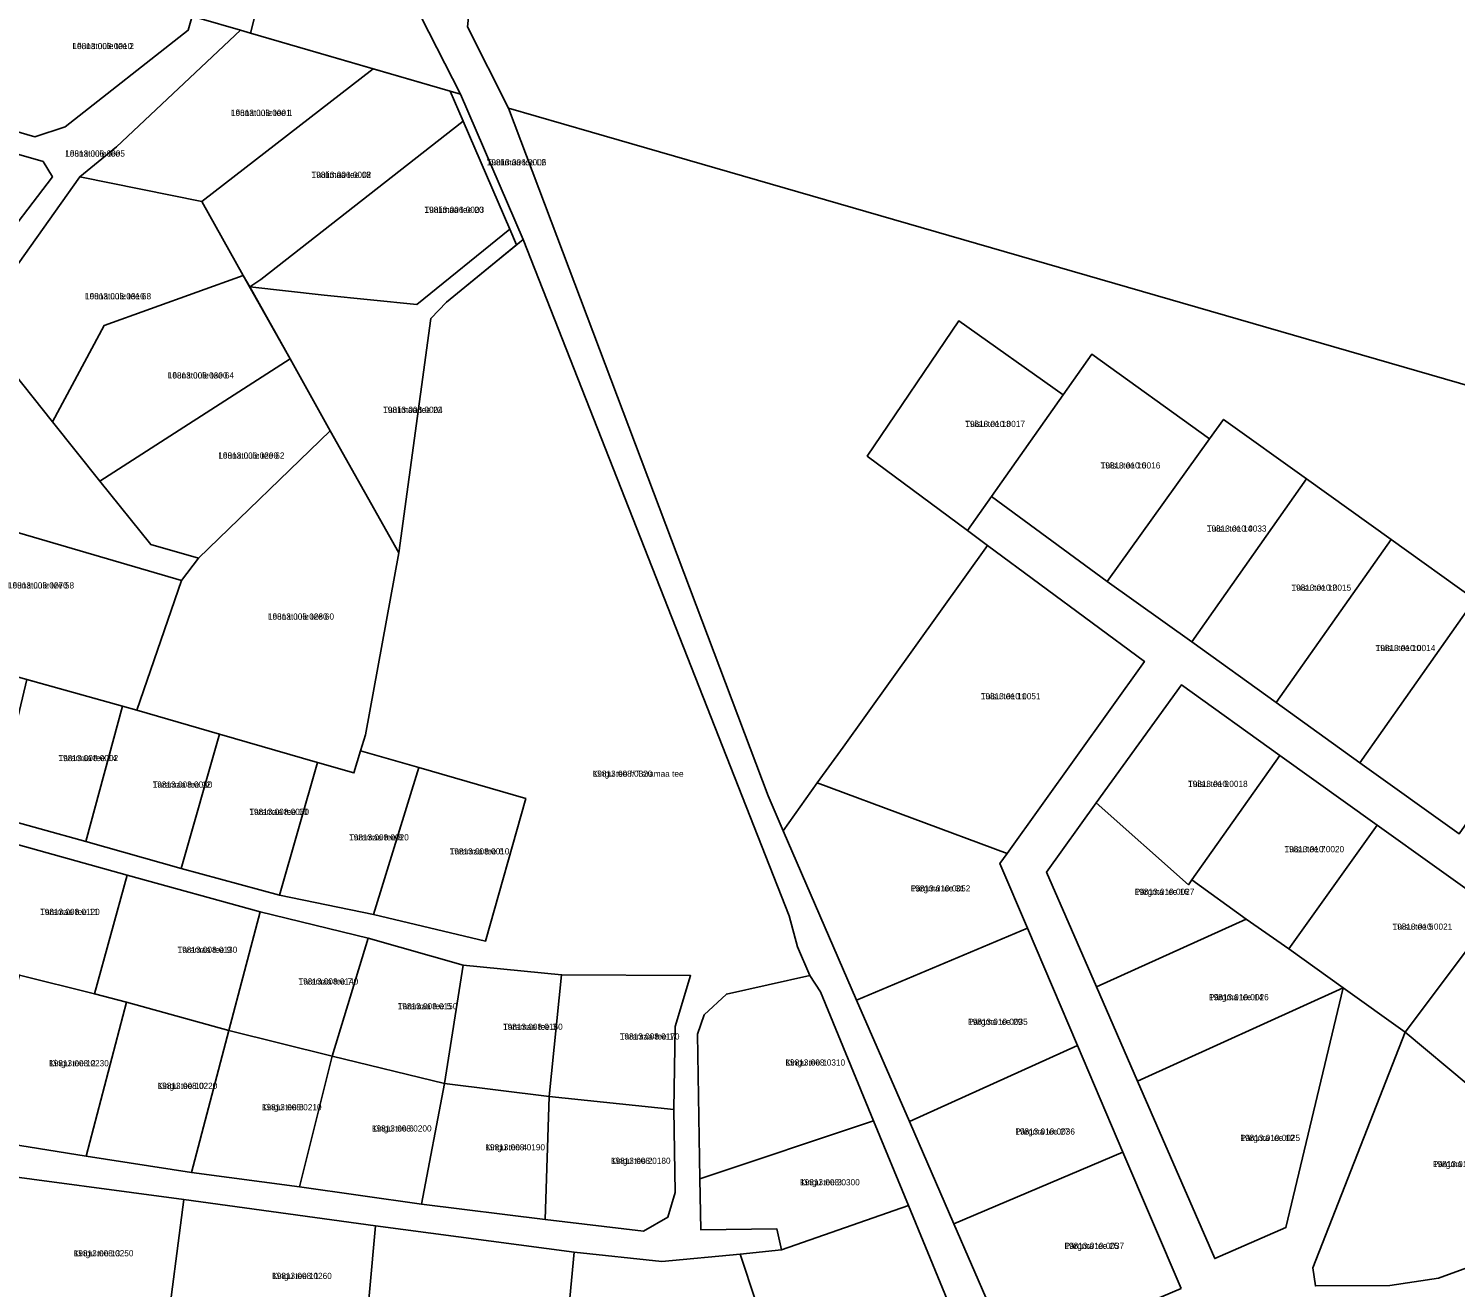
# Model space of a CAD drawing. Extents: x 516875 to 535633, y 6574491 to 6593094.
# Drawn here: x 518002.1 to 518348.7, y 6583536.8 to 6583842.6 of the extents above; entities that cross this region are included whole.
import ezdxf

# ---------------------------------------------------------------- set-up
doc = ezdxf.new("R2010")
doc.units = 0
for name, color, linetype in [('L_AADRESS', 7, 'Continuous'), ('PIIR', 7, 'Continuous'), ('TUNNUS', 7, 'Continuous')]:
    doc.layers.add(name, color=color, linetype=linetype)

msp = doc.modelspace()

# ---------------------------------------------------------------- linework, layer by layer
at = {"layer": 'PIIR'}
for points in [[(518119.68, 6583947.56), (518148.5, 6583950.08), (518165.33, 6583915.79), (518195.67, 6583852.92), (518252, 6583881.49), (518277.31, 6583894.33), (518313.45, 6583912.04), (518337.66, 6583924.16), (518350.53, 6583930.55), (518369.36, 6583908.16), (518395.02, 6583877.64), (518410.83, 6583858.99), (518420.56, 6583835.4), (518428.46, 6583811.8), (518412.68, 6583808.85), (518379.77, 6583802.71), (518366.15, 6583751.74), (518138.79, 6583817.44), (518118.62, 6583823.27), (518108.69, 6583843.02)], [(518055.95, 6583841.51), (518070.47, 6583898.22), (518106.97, 6583826.68)], [(517985.74, 6583821.48), (517996.62, 6583858.9), (518015.14, 6583853.46), (518041.8, 6583845.63), (518040.85, 6583842.21), (518010.97, 6583818.73), (518003.6, 6583816.35)], [(518014.49, 6583806.61), (518023.41, 6583813.86), (518053.55, 6583842.21), (518055.95, 6583841.51), (518085.8, 6583832.84), (518044.11, 6583800.59)], [(518044.11, 6583800.59), (518085.8, 6583832.84), (518104.51, 6583827.4), (518107.64, 6583820.12), (518058.52, 6583781.66), (518055.78, 6583779.84), (518054.22, 6583782.6)], [(518104.51, 6583827.4), (518106.97, 6583826.68), (518122.17, 6583791.38), (518120.58, 6583790.08), (518118.93, 6583793.9), (518107.64, 6583820.12)], [(517964.46, 6583782.19), (517975, 6583819.05), (518005.57, 6583810.32), (518007.86, 6583806.63), (517979.17, 6583768.99)], [(518055.78, 6583779.84), (518058.52, 6583781.66), (518107.64, 6583820.12), (518118.93, 6583793.9), (518096.38, 6583775.57), (518073.9, 6583777.89)], [(518007.89, 6583747.09), (517989.02, 6583770.74), (518014.49, 6583806.61), (518044.11, 6583800.59), (518054.22, 6583782.6), (518020.39, 6583770.47)], [(518055.78, 6583779.84), (518073.9, 6583777.89), (518096.38, 6583775.57), (518118.93, 6583793.9), (518120.58, 6583790.08), (518103.57, 6583776.17), (518099.81, 6583772.15), (518092.03, 6583715.27), (518075.34, 6583744.9), (518065.63, 6583762.37)], [(518007.89, 6583747.09), (518020.39, 6583770.47), (518054.22, 6583782.6), (518065.63, 6583762.37), (518019.38, 6583732.64)], [(518205.78, 6583738.76), (518228.05, 6583771.63), (518253.4, 6583753.68), (518235.99, 6583728.96), (518230.15, 6583720.7)], [(518031.72, 6583717.26), (518019.38, 6583732.64), (518065.63, 6583762.37), (518075.34, 6583744.9), (518043.34, 6583713.93)], [(518253.4, 6583753.68), (518260.34, 6583763.55), (518288.95, 6583742.96), (518264.03, 6583708.34), (518235.99, 6583728.96)], [(518312.5, 6583733.22), (518284.6, 6583693.61), (518264.03, 6583708.34), (518288.95, 6583742.96), (518292.34, 6583747.67)], [(518028.36, 6583677.02), (518039.22, 6583708.54), (518043.34, 6583713.93), (518075.34, 6583744.9), (518092.03, 6583715.27), (518083.9, 6583671.04), (518082.73, 6583667.2), (518081.09, 6583661.82), (518072.24, 6583664.37), (518048.47, 6583671.22)], [(517965.25, 6583736.2), (517983.25, 6583724.94), (518039.22, 6583708.54), (518028.36, 6583677.02), (518024.91, 6583677.99), (517952.8, 6583698.13)], [(518284.6, 6583693.61), (518312.5, 6583733.22), (518333.06, 6583718.48), (518305.14, 6583678.89)], [(518235.01, 6583717.06), (518273.09, 6583688.9), (518239.74, 6583642.24), (518193.65, 6583659.39), (518199.91, 6583668.1)], [(518353.39, 6583703.91), (518325.45, 6583664.29), (518305.14, 6583678.89), (518333.06, 6583718.48)], [(518377.24, 6583686.82), (518349.53, 6583646.99), (518325.45, 6583664.29), (518353.39, 6583703.91)], [(518001.68, 6583684.47), (518024.91, 6583677.99), (518015.95, 6583645.18), (517993.73, 6583651.3)], [(518282.11, 6583683.2), (518261.37, 6583654.52), (518249.36, 6583637.7), (518261.48, 6583609.85), (518271.45, 6583586.92), (518290.19, 6583543.83), (518307.48, 6583551.35), (518321.39, 6583609.64), (518336.44, 6583598.86), (518314.01, 6583541.62), (518314.63, 6583537.2), (518332.71, 6583537.27), (518344.56, 6583539.12), (518357.63, 6583543.89), (518372.37, 6583550.53), (518405.69, 6583565.75), (518388.93, 6583602.34), (518384.82, 6583609.06), (518358.61, 6583628.41), (518329.61, 6583649.1), (518306.01, 6583666.04)], [(518284.65, 6583635.87), (518283.78, 6583634.65), (518261.37, 6583654.52), (518282.11, 6583683.2), (518306.01, 6583666.04)], [(518024.91, 6583677.99), (518028.36, 6583677.02), (518048.47, 6583671.22), (518039.14, 6583638.59), (518015.95, 6583645.18)], [(518048.47, 6583671.22), (518072.24, 6583664.37), (518063.01, 6583632.1), (518039.14, 6583638.59)], [(518072.24, 6583664.37), (518081.09, 6583661.82), (518082.73, 6583667.2), (518096.83, 6583663.12), (518085.85, 6583627.45), (518063.01, 6583632.1)], [(518306.01, 6583666.04), (518329.61, 6583649.1), (518308.18, 6583619.11), (518297.85, 6583626.26), (518284.65, 6583635.87)], [(518096.83, 6583663.12), (518122.85, 6583655.61), (518113.07, 6583620.97), (518085.85, 6583627.45)], [(518193.65, 6583659.39), (518239.74, 6583642.24), (518238, 6583639.81), (518244.68, 6583624.13), (518203.2, 6583606.62), (518185.32, 6583647.76)], [(518283.78, 6583634.65), (518284.65, 6583635.87), (518297.85, 6583626.26), (518261.48, 6583609.85), (518249.36, 6583637.7), (518261.37, 6583654.52)], [(518358.61, 6583628.41), (518336.44, 6583598.86), (518321.39, 6583609.64), (518308.18, 6583619.11), (518329.61, 6583649.1)], [(517982.9, 6583615.4), (517992.02, 6583646.47), (518025.99, 6583637), (518018.05, 6583608.13), (517999.87, 6583612.71)], [(518018.05, 6583608.13), (518025.99, 6583637), (518058.33, 6583628.04), (518050.72, 6583599.22), (518025.85, 6583606.16)], [(518058.33, 6583628.04), (518084.57, 6583621.7), (518075.8, 6583593), (518050.72, 6583599.22)], [(518384.82, 6583609.06), (518388.93, 6583602.34), (518354.21, 6583587.15), (518351.72, 6583586.06), (518336.44, 6583598.86), (518358.61, 6583628.41)], [(518256.84, 6583595.61), (518216.03, 6583577.1), (518203.2, 6583606.62), (518244.68, 6583624.13)], [(518308.18, 6583619.11), (518321.39, 6583609.64), (518271.45, 6583586.92), (518261.48, 6583609.85), (518297.85, 6583626.26)], [(518084.57, 6583621.7), (518107.66, 6583615.14), (518103.08, 6583586.36), (518075.8, 6583593)], [(517999.87, 6583612.71), (518018.05, 6583608.13), (518025.85, 6583606.16), (518016.08, 6583568.73), (517988.26, 6583573.2)], [(518107.66, 6583615.14), (518131.52, 6583612.77), (518128.49, 6583583.23), (518103.08, 6583586.36)], [(518131.52, 6583612.77), (518162.86, 6583612.56), (518159.13, 6583600.22), (518158.79, 6583580.04), (518128.49, 6583583.23)], [(518164.52, 6583598.34), (518166.18, 6583603.04), (518171.58, 6583608.1), (518191.8, 6583612.62), (518194.41, 6583608.65), (518207.3, 6583577.32), (518165.14, 6583563.17)], [(518307.48, 6583551.35), (518290.19, 6583543.83), (518271.45, 6583586.92), (518321.39, 6583609.64)], [(518025.85, 6583606.16), (518050.72, 6583599.22), (518041.66, 6583564.76), (518016.08, 6583568.73)], [(518050.72, 6583599.22), (518075.8, 6583593), (518067.84, 6583561.28), (518041.66, 6583564.76)], [(518351.72, 6583586.06), (518354.21, 6583587.15), (518372.37, 6583550.53), (518357.63, 6583543.89), (518344.56, 6583539.12), (518332.71, 6583537.27), (518314.63, 6583537.2), (518314.01, 6583541.62), (518336.44, 6583598.86)], [(518267.87, 6583569.7), (518226.8, 6583552.31), (518216.03, 6583577.1), (518256.84, 6583595.61)], [(518075.8, 6583593), (518103.08, 6583586.36), (518097.53, 6583557.03), (518067.84, 6583561.28)], [(518103.08, 6583586.36), (518128.49, 6583583.23), (518127.58, 6583553.32), (518097.53, 6583557.03)], [(518128.49, 6583583.23), (518158.79, 6583580.04), (518159.15, 6583559.91), (518157.32, 6583553.86), (518151.41, 6583550.46), (518127.58, 6583553.32)], [(518183.8, 6583551.1), (518165.36, 6583550.8), (518165.14, 6583563.17), (518207.3, 6583577.32), (518215.77, 6583556.7), (518184.92, 6583545.95)], [(518282.02, 6583536.54), (518252.26, 6583523.93), (518239.67, 6583522.67), (518226.8, 6583552.31), (518267.87, 6583569.7)], [(517990.05, 6583564.86), (518039.75, 6583558.17), (518035.35, 6583523.9), (517986.57, 6583528.25)], [(518039.75, 6583558.17), (518086.33, 6583551.78), (518083.42, 6583519.61), (518035.35, 6583523.9)], [(518174.88, 6583544.93), (518184.92, 6583545.95), (518215.77, 6583556.7), (518232.29, 6583516.55), (518231.48, 6583512.69), (518229.22, 6583508.9), (518226.28, 6583506.86), (518186.36, 6583510.43)], [(518086.33, 6583551.78), (518134.58, 6583545.36), (518131.79, 6583515.29), (518083.42, 6583519.61)], [(518134.58, 6583545.36), (518155.86, 6583543.14), (518174.88, 6583544.93), (518186.36, 6583510.43), (518131.79, 6583515.29)]]:
    msp.add_lwpolyline(points, close=True, dxfattribs=at)
for points in [[(518232.29, 6583516.55), (518215.77, 6583556.7), (518207.3, 6583577.32), (518194.41, 6583608.65), (518191.8, 6583612.62), (518188.85, 6583619.6), (518186.83, 6583627.11), (518122.17, 6583791.38), (518106.97, 6583826.68), (518070.47, 6583898.22), (518055.95, 6583841.51), (518053.55, 6583842.21), (518043.38, 6583845.17)], [(517985.74, 6583821.48), (518003.6, 6583816.35), (518010.97, 6583818.73), (518040.85, 6583842.21), (518041.8, 6583845.63), (518043.38, 6583845.17), (518053.55, 6583842.21), (518023.41, 6583813.86), (518014.49, 6583806.61), (517989.02, 6583770.74), (518007.89, 6583747.09), (518019.38, 6583732.64), (518031.72, 6583717.26), (518043.34, 6583713.93), (518039.22, 6583708.54), (517983.25, 6583724.94)], [(518108.69, 6583843.02), (518118.62, 6583823.27), (518181.72, 6583656.25), (518185.32, 6583647.76), (518203.2, 6583606.62), (518216.03, 6583577.1), (518226.8, 6583552.31), (518239.67, 6583522.67)], [(518353.39, 6583703.91), (518333.06, 6583718.48), (518312.5, 6583733.22), (518292.34, 6583747.67), (518288.95, 6583742.96), (518260.34, 6583763.55), (518253.4, 6583753.68), (518228.05, 6583771.63), (518205.78, 6583738.76), (518230.15, 6583720.7), (518235.01, 6583717.06), (518199.91, 6583668.1), (518193.65, 6583659.39), (518185.32, 6583647.76), (518181.72, 6583656.25), (518118.62, 6583823.27), (518138.79, 6583817.44), (518366.15, 6583751.74)], [(517979.17, 6583768.99), (518007.86, 6583806.63), (518005.57, 6583810.32), (517975, 6583819.05)], [(517993.73, 6583651.3), (518015.95, 6583645.18), (518039.14, 6583638.59), (518063.01, 6583632.1), (518085.85, 6583627.45), (518113.07, 6583620.97), (518122.85, 6583655.61), (518096.83, 6583663.12), (518082.73, 6583667.2), (518083.9, 6583671.04), (518092.03, 6583715.27), (518099.81, 6583772.15), (518103.57, 6583776.17), (518122.17, 6583791.38), (518186.83, 6583627.11), (518188.85, 6583619.6), (518191.8, 6583612.62), (518171.58, 6583608.1), (518166.18, 6583603.04), (518164.52, 6583598.34), (518165.14, 6583563.17), (518165.36, 6583550.8), (518183.8, 6583551.1), (518184.92, 6583545.95), (518174.88, 6583544.93), (518155.86, 6583543.14), (518134.58, 6583545.36), (518086.33, 6583551.78), (518039.75, 6583558.17), (517990.05, 6583564.86)], [(518282.02, 6583536.54), (518267.87, 6583569.7), (518256.84, 6583595.61), (518244.68, 6583624.13), (518238, 6583639.81), (518239.74, 6583642.24), (518273.09, 6583688.9), (518235.01, 6583717.06), (518230.15, 6583720.7), (518235.99, 6583728.96), (518264.03, 6583708.34), (518284.6, 6583693.61), (518305.14, 6583678.89), (518325.45, 6583664.29), (518349.53, 6583646.99)], [(517988.26, 6583573.2), (518016.08, 6583568.73), (518041.66, 6583564.76), (518067.84, 6583561.28), (518097.53, 6583557.03), (518127.58, 6583553.32), (518151.41, 6583550.46), (518157.32, 6583553.86), (518159.15, 6583559.91), (518158.79, 6583580.04), (518159.13, 6583600.22), (518162.86, 6583612.56), (518131.52, 6583612.77), (518107.66, 6583615.14), (518084.57, 6583621.7), (518058.33, 6583628.04), (518025.99, 6583637), (517992.02, 6583646.47)]]:
    msp.add_lwpolyline(points, dxfattribs=at)

# ---------------------------------------------------------------- texts
at = {"layer": 'L_AADRESS'}
for s, p in [('Lõunatuule tee 2', (518012.72, 6583837.62)), ('Lõunatuule tee 1', (518051.22, 6583821.4)), ('Lõunatuule tee', (518010.96, 6583811.51)), ('Tuulimaa tee L2', (518113.34, 6583809.38)), ('Tuulimaa tee 18', (518070.79, 6583806.34)), ('Tuulimaa tee 20', (518098.21, 6583797.85)), ('Lõunatuule tee 68', (518015.77, 6583776.85)), ('Lõunatuule tee 64', (518035.88, 6583757.62)), ('Tuulimaa tee 22', (518088.18, 6583749.26)), ('Tuisu tee 18', (518229.59, 6583745.83)), ('Lõunatuule tee 62', (518048.16, 6583738.15)), ('Tuisu tee 16', (518262.47, 6583735.75)), ('Tuisu tee 14', (518288.27, 6583720.41)), ('Lõunatuule tee 58', (517997.06, 6583706.61)), ('Tuisu tee 12', (518308.83, 6583706.07)), ('Lõunatuule tee 60', (518060.2, 6583699.04)), ('Tuisu tee 10', (518329.27, 6583691.4)), ('Tuisu tee 11', (518233.37, 6583679.69)), ('Taramaa tee 14', (518009.32, 6583664.67)), ('Kingu tee // Taramaa tee', (518139.09, 6583660.87)), ('Taramaa tee 12', (518032.21, 6583658.23)), ('Tuisu tee 9', (518283.69, 6583658.4)), ('Taramaa tee 10', (518055.69, 6583651.61)), ('Taramaa tee 8', (518079.92, 6583645.41)), ('Tuisu tee 7', (518307.13, 6583642.54)), ('Taramaa tee 6', (518104.35, 6583642)), ('Pärgma tee 31', (518216.32, 6583633.01)), ('Pärgma tee 16', (518270.74, 6583632.19)), ('Taramaa tee 11', (518004.86, 6583627.3)), ('Tuisu tee 5', (518333.39, 6583623.72)), ('Taramaa tee 9', (518038.25, 6583618.11)), ('Taramaa tee 7', (518067.64, 6583610.41)), ('Taramaa tee 5', (518091.73, 6583604.39)), ('Pärgma tee 14', (518288.79, 6583606.59)), ('Pärgma tee 29', (518230.26, 6583600.62)), ('Taramaa tee 3', (518117.3, 6583599.4)), ('Taramaa tee 1', (518145.68, 6583597.05)), ('Kingu tee 12', (518007.05, 6583590.54)), ('Kingu tee 1', (518185.91, 6583590.72)), ('Kingu tee 10', (518033.4, 6583585.05)), ('Kingu tee 8', (518058.73, 6583579.86)), ('Kingu tee 6', (518085.46, 6583574.7)), ('Pärgma tee 27', (518241.73, 6583573.96)), ('Kingu tee 4', (518113.01, 6583570.13)), ('Pärgma tee 12', (518296.42, 6583572.41)), ('Kingu tee 2', (518143.51, 6583566.85)), ('Pärgma tee 10', (518343.19, 6583566.06)), ('Kingu tee 3', (518189.46, 6583561.63)), ('Pärgma tee 25', (518253.68, 6583546.19)), ('Kingu tee 13', (518013.04, 6583544.38)), ('Kingu tee 11', (518061.22, 6583538.89))]:
    msp.add_text(s, height=1.5, dxfattribs=at).set_placement(p)
at = {"layer": 'TUNNUS'}
for s, p in [('19813:006:0010', (518012.72, 6583837.62)), ('19813:006:0001', (518051.22, 6583821.4)), ('19813:006:0005', (518010.96, 6583811.51)), ('19813:006:0006', (518113.34, 6583809.38)), ('19813:006:0002', (518070.79, 6583806.34)), ('19813:006:0003', (518098.21, 6583797.85)), ('19813:006:0310', (518015.77, 6583776.85)), ('19813:006:0300', (518035.88, 6583757.62)), ('19813:006:0004', (518088.18, 6583749.26)), ('19813:010:0017', (518229.59, 6583745.83)), ('19813:006:0290', (518048.16, 6583738.15)), ('19813:010:0016', (518262.47, 6583735.75)), ('19813:010:0033', (518288.27, 6583720.41)), ('19813:006:0270', (517997.06, 6583706.61)), ('19813:010:0015', (518308.83, 6583706.07)), ('19813:006:0280', (518060.2, 6583699.04)), ('19813:010:0014', (518329.27, 6583691.4)), ('19813:010:0051', (518233.37, 6583679.69)), ('19813:008:0002', (518009.32, 6583664.67)), ('19813:008:0320', (518139.09, 6583660.87)), ('19813:008:0040', (518032.21, 6583658.23)), ('19813:010:0018', (518283.69, 6583658.4)), ('19813:008:0030', (518055.69, 6583651.61)), ('19813:008:0020', (518079.92, 6583645.41)), ('19813:010:0020', (518307.13, 6583642.54)), ('19813:008:0010', (518104.35, 6583642)), ('19813:010:0052', (518216.32, 6583633.01)), ('19813:010:0027', (518270.74, 6583632.19)), ('19813:008:0120', (518004.86, 6583627.3)), ('19813:010:0021', (518333.39, 6583623.72)), ('19813:008:0130', (518038.25, 6583618.11)), ('19813:008:0140', (518067.64, 6583610.41)), ('19813:008:0150', (518091.73, 6583604.39)), ('19813:010:0026', (518288.79, 6583606.59)), ('19813:010:0035', (518230.26, 6583600.62)), ('19813:008:0160', (518117.3, 6583599.4)), ('19813:008:0170', (518145.68, 6583597.05)), ('19813:008:0230', (518007.05, 6583590.54)), ('19813:008:0310', (518185.91, 6583590.72)), ('19813:008:0220', (518033.4, 6583585.05)), ('19813:008:0210', (518058.73, 6583579.86)), ('19813:008:0200', (518085.46, 6583574.7)), ('19813:010:0036', (518241.73, 6583573.96)), ('19813:008:0190', (518113.01, 6583570.13)), ('19813:010:0025', (518296.42, 6583572.41)), ('19813:008:0180', (518143.51, 6583566.85)), ('19813:010:0024', (518343.19, 6583566.06)), ('19813:008:0300', (518189.46, 6583561.63)), ('19813:010:0037', (518253.68, 6583546.19)), ('19813:008:0250', (518013.04, 6583544.38)), ('19813:008:0260', (518061.22, 6583538.89))]:
    msp.add_text(s, height=1.5, dxfattribs=at).set_placement(p)

doc.saveas('drawing.dxf')
